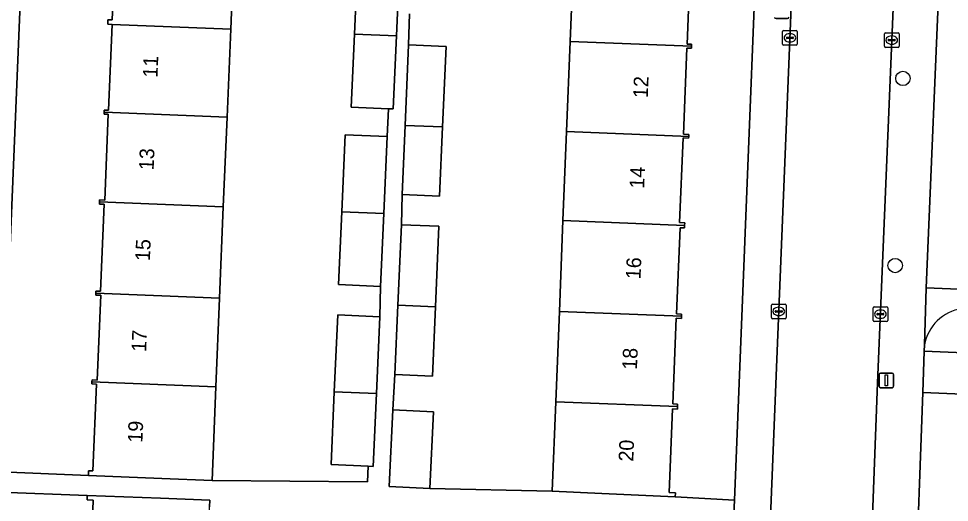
# Model space of a CAD drawing. Extents: x 160077 to 160948, y 386481 to 387498.
# Drawn here: x 160622.7 to 160686, y 386691.3 to 386724.2 of the extents above; entities that cross this region are included whole.
import ezdxf

# ---------------------------------------------------------------- set-up
doc = ezdxf.new("R2010")
doc.units = 0
for name, color, linetype in [('IMGEO_Boom', 7, 'Continuous'), ('IMGEO_Erf', 7, 'Continuous'), ('IMGEO_Groenvoorziening', 7, 'Continuous'), ('IMGEO_Kolk', 7, 'Continuous'), ('IMGEO_Lichtmast', 7, 'Continuous'), ('IMGEO_Pand', 7, 'Continuous'), ('IMGEO_Pand_nummerreeks', 7, 'Continuous'), ('IMGEO_Rijbaan_lokaal_open', 7, 'Continuous'), ('IMGEO_Voetpad_open', 7, 'Continuous')]:
    doc.layers.add(name, color=color, linetype=linetype)

msp = doc.modelspace()

# ---------------------------------------------------------------- linework, layer by layer
at = {"layer": 'IMGEO_Boom'}
for centre in [(160682.808, 386720.149), (160682.283, 386707.415)]:
    msp.add_circle(centre, 0.489, dxfattribs=at)
at = {"layer": 'IMGEO_Erf'}
for points in [[(160623.787, 386750), (160621.452, 386693.374), (160627.397, 386693.129), (160627.41, 386693.441), (160627.708, 386693.429), (160627.952, 386699.339), (160627.638, 386699.352), (160627.643, 386699.488), (160627.649, 386699.626), (160627.997, 386699.612), (160628.236, 386705.391), (160627.894, 386705.405), (160627.9, 386705.54), (160627.905, 386705.673), (160628.224, 386705.66), (160628.469, 386711.586), (160628.148, 386711.6), (160628.154, 386711.745), (160628.16, 386711.888), (160628.508, 386711.873), (160628.749, 386717.71), (160628.463, 386717.722), (160628.469, 386717.858), (160628.475, 386717.996), (160628.772, 386717.984), (160629.013, 386723.822), (160628.715, 386723.835), (160628.728, 386724.144), (160629.025, 386724.132), (160629.27, 386730.05)], [(160668.365, 386728.354), (160668.125, 386722.49), (160668.427, 386722.478), (160668.422, 386722.34), (160668.416, 386722.201), (160668.116, 386722.214), (160667.876, 386716.349), (160668.242, 386716.334), (160668.237, 386716.208), (160668.232, 386716.082), (160667.852, 386716.098), (160667.616, 386710.334), (160667.969, 386710.319), (160667.962, 386710.148), (160667.955, 386709.976), (160667.658, 386709.988), (160667.418, 386704.12), (160667.753, 386704.106), (160667.747, 386703.96), (160667.741, 386703.816), (160667.389, 386703.831), (160667.15, 386697.993), (160667.482, 386697.979), (160667.475, 386697.812), (160667.468, 386697.643), (160667.139, 386697.657), (160666.903, 386691.954), (160667.328, 386691.943), (160667.313, 386691.674), (160671.348, 386691.449), (160673.697, 386750)], [(160637.34, 386729.848), (160637.078, 386723.497), (160636.831, 386717.521), (160636.578, 386711.405), (160636.321, 386705.201), (160636.071, 386699.149), (160635.808, 386692.782), (160646.388, 386692.681), (160646.436, 386693.756), (160643.906, 386693.869), (160644.128, 386698.825), (160644.362, 386704.061), (160647.222, 386703.933), (160647.277, 386705.998), (160644.417, 386706.126), (160644.638, 386711.08), (160644.873, 386716.318), (160647.733, 386716.19), (160647.818, 386718.089), (160645.276, 386718.203), (160645.497, 386723.158), (160645.732, 386728.395)], [(160649.242, 386724.541), (160649.183, 386722.441), (160651.73, 386722.333), (160651.496, 386716.857), (160651.295, 386712.14), (160648.748, 386712.249), (160648.691, 386710.193), (160651.238, 386710.085), (160651.004, 386704.609), (160650.803, 386699.892), (160648.256, 386700.001), (160648.111, 386697.598), (160650.866, 386697.466), (160650.618, 386692.246), (160658.945, 386692.053), (160659.189, 386698.133), (160659.437, 386704.282), (160659.685, 386710.469), (160659.929, 386716.53), (160660.175, 386722.66), (160660.423, 386728.822)], [(160627.51, 386685.613), (160627.726, 386691.449), (160627.307, 386691.464), (160627.318, 386691.759), (160621.394, 386691.978)]]:
    msp.add_lwpolyline(points, dxfattribs=at)
msp.add_lwpolyline([(160733.266, 386727.02), (160685.358, 386729.013), (160684.392, 386705.888), (160736.599, 386703.746)], close=True, dxfattribs=at)
at = {"layer": 'IMGEO_Groenvoorziening'}
for points in [[(160684.282, 386702.016), (160684.265, 386701.578), (160734.304, 386699.5), (160737.203, 386679.324)], [(160686.48, 386681.453), (160733.424, 386679.476), (160732.433, 386685.483), (160721.665, 386685.947), (160722.073, 386696.59), (160730.668, 386696.179), (160730.558, 386696.843), (160684.161, 386698.783), (160683.645, 386684.533)]]:
    msp.add_lwpolyline(points, dxfattribs=at)
msp.add_lwpolyline([(160737.203, 386679.324), (160734.304, 386699.5), (160684.265, 386701.578), (160684.161, 386698.783), (160730.558, 386696.843), (160730.668, 386696.179), (160731.672, 386690.1), (160732.433, 386685.483), (160733.424, 386679.476), (160737.065, 386679.326), (160737.134, 386679.324)], close=True, dxfattribs=at)
msp.add_arc((160687.245, 386701.5), 3.007, 98.40657, 170.12144, dxfattribs=at)
at = {"layer": 'IMGEO_Kolk'}
for p, q in [((160674.62, 386722.485), (160674.62, 386723.337)), ((160674.695, 386723.411), (160675.547, 386723.411)), ((160674.879, 386722.905), (160674.879, 386722.917)), ((160675.317, 386722.868), (160674.919, 386722.868)), ((160674.922, 386722.954), (160675.32, 386722.954)), ((160675.108, 386723.191), (160675.133, 386723.191)), ((160675.363, 386722.917), (160675.363, 386722.905)), ((160675.621, 386723.337), (160675.621, 386722.485)), ((160681.55, 386722.337), (160681.55, 386723.189)), ((160681.625, 386723.263), (160682.477, 386723.263)), ((160681.852, 386722.806), (160682.25, 386722.806)), ((160682.038, 386723.043), (160682.063, 386723.043)), ((160682.551, 386723.189), (160682.551, 386722.337)), ((160675.547, 386722.411), (160674.695, 386722.411)), ((160675.131, 386722.631), (160675.106, 386722.631)), ((160682.477, 386722.263), (160681.625, 386722.263)), ((160681.809, 386722.757), (160681.809, 386722.769)), ((160682.247, 386722.72), (160681.849, 386722.72)), ((160682.061, 386722.483), (160682.036, 386722.483)), ((160682.293, 386722.769), (160682.293, 386722.757)), ((160673.864, 386703.867), (160673.864, 386704.719)), ((160673.939, 386704.793), (160674.791, 386704.793)), ((160674.352, 386704.573), (160674.377, 386704.573)), ((160674.865, 386704.719), (160674.865, 386703.867)), ((160680.775, 386703.68), (160680.775, 386704.532)), ((160680.85, 386704.606), (160681.702, 386704.606)), ((160681.776, 386704.532), (160681.776, 386703.68)), ((160674.123, 386704.287), (160674.123, 386704.299)), ((160674.561, 386704.25), (160674.163, 386704.25)), ((160674.166, 386704.336), (160674.564, 386704.336)), ((160674.375, 386704.013), (160674.35, 386704.013)), ((160674.607, 386704.299), (160674.607, 386704.287)), ((160681.034, 386704.1), (160681.034, 386704.112)), ((160681.472, 386704.063), (160681.074, 386704.063)), ((160681.077, 386704.149), (160681.475, 386704.149)), ((160681.286, 386703.826), (160681.261, 386703.826)), ((160681.263, 386704.386), (160681.288, 386704.386)), ((160681.518, 386704.112), (160681.518, 386704.1)), ((160674.791, 386703.793), (160673.939, 386703.793)), ((160681.702, 386703.606), (160680.85, 386703.606))]:
    msp.add_line(p, q, dxfattribs=at)
for points in [[(160674.62, 386722.485), (160674.62, 386723.337)], [(160674.695, 386723.411), (160675.547, 386723.411)], [(160675.621, 386723.337), (160675.621, 386722.485)], [(160681.55, 386722.337), (160681.55, 386723.189)], [(160681.625, 386723.263), (160682.477, 386723.263)], [(160682.551, 386723.189), (160682.551, 386722.337)], [(160675.547, 386722.411), (160674.695, 386722.411)], [(160682.477, 386722.263), (160681.625, 386722.263)], [(160673.864, 386703.867), (160673.864, 386704.719)], [(160673.939, 386704.793), (160674.791, 386704.793)], [(160674.865, 386704.719), (160674.865, 386703.867)], [(160680.775, 386703.68), (160680.775, 386704.532)], [(160680.85, 386704.606), (160681.702, 386704.606)], [(160681.776, 386704.532), (160681.776, 386703.68)], [(160674.791, 386703.793), (160673.939, 386703.793)], [(160681.702, 386703.606), (160680.85, 386703.606)]]:
    msp.add_lwpolyline(points, dxfattribs=at)
for centre, radius, start, end in [((160674.697, 386723.335), 0.0765, 91.55205, 178.44795), ((160674.697, 386723.335), 0.0765, 91.55205, 178.44795), ((160674.919, 386722.914), 0.0403, 85.87752, 175.75265), ((160674.916, 386722.904), 0.0366, 178.93798, 274.71019), ((160675.32, 386722.911), 0.043, 264.86636, 352.45326), ((160675.324, 386722.916), 0.0386, 1.73085, 96.63898), ((160675.545, 386723.335), 0.0765, 1.55205, 88.44795), ((160675.545, 386723.335), 0.0765, 1.55205, 88.44795), ((160681.627, 386723.187), 0.0765, 91.55205, 178.44795), ((160681.627, 386723.187), 0.0765, 91.55205, 178.44795), ((160681.849, 386722.766), 0.0403, 85.87752, 175.75265), ((160682.254, 386722.768), 0.0386, 1.73085, 96.63898), ((160682.475, 386723.187), 0.0765, 1.55205, 88.44795), ((160682.475, 386723.187), 0.0765, 1.55205, 88.44795), ((160674.697, 386722.487), 0.0765, 181.55205, 268.44795), ((160674.697, 386722.487), 0.0765, 181.55205, 268.44795), ((160675.545, 386722.487), 0.0765, 271.55205, 358.44795), ((160675.545, 386722.487), 0.0765, 271.55205, 358.44795), ((160681.627, 386722.339), 0.0765, 181.55205, 268.44795), ((160681.627, 386722.339), 0.0765, 181.55205, 268.44795), ((160681.846, 386722.756), 0.0366, 178.93798, 274.71019), ((160682.25, 386722.763), 0.043, 264.86636, 352.45326), ((160682.475, 386722.339), 0.0765, 271.55205, 358.44795), ((160682.475, 386722.339), 0.0765, 271.55205, 358.44795), ((160673.941, 386704.717), 0.0765, 91.55205, 178.44795), ((160673.941, 386704.717), 0.0765, 91.55205, 178.44795), ((160674.789, 386704.717), 0.0765, 1.55205, 88.44795), ((160674.789, 386704.717), 0.0765, 1.55205, 88.44795), ((160680.852, 386704.53), 0.0765, 91.55205, 178.44795), ((160680.852, 386704.53), 0.0765, 91.55205, 178.44795), ((160681.7, 386704.53), 0.0765, 1.55205, 88.44795), ((160681.7, 386704.53), 0.0765, 1.55205, 88.44795), ((160673.941, 386703.869), 0.0765, 181.55205, 268.44795), ((160673.941, 386703.869), 0.0765, 181.55205, 268.44795), ((160674.163, 386704.296), 0.0403, 85.87752, 175.75265), ((160674.16, 386704.286), 0.0366, 178.93798, 274.71019), ((160674.564, 386704.293), 0.043, 264.86636, 352.45326), ((160674.568, 386704.298), 0.0386, 1.73085, 96.63898), ((160674.789, 386703.869), 0.0765, 271.55205, 358.44795), ((160674.789, 386703.869), 0.0765, 271.55205, 358.44795), ((160681.074, 386704.109), 0.0403, 85.87752, 175.75265), ((160681.071, 386704.099), 0.0366, 178.93798, 274.71019), ((160681.475, 386704.106), 0.043, 264.86636, 352.45326), ((160681.479, 386704.111), 0.0386, 1.73085, 96.63898), ((160680.852, 386703.682), 0.0765, 181.55205, 268.44795), ((160680.852, 386703.682), 0.0765, 181.55205, 268.44795), ((160681.7, 386703.682), 0.0765, 271.55205, 358.44795), ((160681.7, 386703.682), 0.0765, 271.55205, 358.44795)]:
    msp.add_arc(centre, radius, start, end, dxfattribs=at)
for centre, major_axis, ratio, start_param, end_param in [((160675.107, 386722.911), (-0.387, 0.002), 0.722429, 4.712389, 7.853982), ((160675.132, 386722.911), (-0.39, 0.002), 0.717154, 1.570796, 4.712389), ((160682.037, 386722.763), (-0.387, 0.002), 0.722429, 4.712389, 7.853982), ((160682.062, 386722.763), (-0.39, 0.002), 0.717154, 1.570796, 4.712389), ((160674.351, 386704.293), (-0.387, 0.002), 0.722429, 4.712389, 7.853982), ((160674.376, 386704.293), (-0.39, 0.002), 0.717154, 1.570796, 4.712389), ((160681.262, 386704.106), (-0.387, 0.002), 0.722429, 4.712389, 7.853982), ((160681.287, 386704.106), (-0.39, 0.002), 0.717154, 1.570796, 4.712389)]:
    msp.add_ellipse(centre, major_axis=major_axis, ratio=ratio, start_param=start_param, end_param=end_param, dxfattribs=at)
at = {"layer": 'IMGEO_Lichtmast'}
for p, q in [((160674.966, 386724.222), (160674.176, 386724.222)), ((160674.176, 386724.222), (160674.966, 386724.222)), ((160681.286, 386700.097), (160682.076, 386700.097)), ((160682.076, 386700.097), (160681.286, 386700.097)), ((160681.186, 386699.197), (160681.186, 386699.997)), ((160681.186, 386699.997), (160681.186, 386699.197)), ((160682.176, 386699.997), (160682.176, 386699.197)), ((160682.176, 386699.197), (160682.176, 386699.997)), ((160682.076, 386699.097), (160681.286, 386699.097)), ((160681.286, 386699.097), (160682.076, 386699.097))]:
    msp.add_line(p, q, dxfattribs=at)
msp.add_lwpolyline([(160681.606, 386699.972), (160681.756, 386699.972), (160681.756, 386699.222), (160681.606, 386699.222), (160681.606, 386699.972)], dxfattribs=at)
for centre, start, end in [((160674.176, 386724.322), 180, 270), ((160674.176, 386724.322), 180, 270), ((160674.966, 386724.322), 270, 0), ((160674.966, 386724.322), 270, 0), ((160681.286, 386699.997), 90, 180), ((160681.286, 386699.997), 90, 180), ((160682.076, 386699.997), 0, 90), ((160682.076, 386699.997), 360, 90), ((160681.286, 386699.197), 180, 270), ((160681.286, 386699.197), 180, 270), ((160682.076, 386699.197), 270, 0), ((160682.076, 386699.197), 270, 0)]:
    msp.add_arc(centre, 0.1, start, end, dxfattribs=at)
at = {"layer": 'IMGEO_Pand'}
for points in [[(160628.956, 386730.185), (160628.951, 386730.064), (160629.27, 386730.05), (160629.025, 386724.132), (160628.728, 386724.144), (160628.715, 386723.835), (160629.013, 386723.822), (160637.078, 386723.497), (160637.34, 386729.848)], [(160660.423, 386728.822), (160660.175, 386722.66), (160668.422, 386722.34), (160668.427, 386722.478), (160668.125, 386722.49), (160668.365, 386728.354), (160668.721, 386728.34), (160668.728, 386728.5)], [(160648.592, 386728.267), (160648.001, 386728.293), (160645.732, 386728.395), (160645.497, 386723.158), (160648.359, 386723.042)], [(160629.013, 386723.822), (160628.772, 386717.984), (160628.475, 386717.996), (160628.469, 386717.858), (160636.831, 386717.521), (160637.078, 386723.497)], [(160648.359, 386723.042), (160645.497, 386723.158), (160645.276, 386718.203), (160647.818, 386718.089), (160648.136, 386718.075)], [(160651.73, 386722.333), (160649.183, 386722.441), (160648.949, 386716.956), (160651.496, 386716.857)], [(160668.237, 386716.208), (160668.242, 386716.334), (160667.876, 386716.349), (160668.116, 386722.214), (160668.416, 386722.201), (160668.422, 386722.34), (160660.175, 386722.66), (160659.929, 386716.53)], [(160636.578, 386711.405), (160636.831, 386717.521), (160628.469, 386717.858), (160628.463, 386717.722), (160628.749, 386717.71), (160628.508, 386711.873), (160628.16, 386711.888), (160628.154, 386711.745)], [(160648.748, 386712.249), (160651.295, 386712.14), (160651.496, 386716.857), (160648.949, 386716.956)], [(160667.962, 386710.148), (160667.969, 386710.319), (160667.616, 386710.334), (160667.852, 386716.098), (160668.232, 386716.082), (160668.237, 386716.208), (160659.929, 386716.53), (160659.685, 386710.469)], [(160647.733, 386716.19), (160644.873, 386716.318), (160644.638, 386711.08), (160647.5, 386710.964)], [(160628.154, 386711.745), (160628.148, 386711.6), (160628.469, 386711.586), (160628.224, 386705.66), (160627.905, 386705.673), (160627.9, 386705.54), (160636.321, 386705.201), (160636.578, 386711.405)], [(160644.417, 386706.126), (160647.277, 386705.998), (160647.5, 386710.964), (160644.638, 386711.08)], [(160651.238, 386710.085), (160648.691, 386710.193), (160648.457, 386704.707), (160651.004, 386704.609)], [(160667.747, 386703.96), (160667.753, 386704.106), (160667.418, 386704.12), (160667.658, 386709.988), (160667.955, 386709.976), (160667.962, 386710.148), (160659.685, 386710.469), (160659.437, 386704.282)], [(160627.9, 386705.54), (160627.894, 386705.405), (160628.236, 386705.391), (160627.997, 386699.612), (160627.649, 386699.626), (160627.643, 386699.488), (160636.071, 386699.149), (160636.321, 386705.201)], [(160648.256, 386700.001), (160650.803, 386699.892), (160651.004, 386704.609), (160648.457, 386704.707)], [(160647.222, 386703.933), (160644.362, 386704.061), (160644.128, 386698.825), (160646.989, 386698.71)], [(160667.475, 386697.812), (160667.482, 386697.979), (160667.15, 386697.993), (160667.389, 386703.831), (160667.741, 386703.816), (160667.747, 386703.96), (160659.437, 386704.282), (160659.189, 386698.133)], [(160627.643, 386699.488), (160627.638, 386699.352), (160627.952, 386699.339), (160627.708, 386693.429), (160627.41, 386693.441), (160627.397, 386693.129), (160632.393, 386692.923), (160635.808, 386692.782), (160636.071, 386699.149)], [(160646.989, 386698.71), (160644.128, 386698.825), (160643.906, 386693.869), (160646.436, 386693.756), (160646.766, 386693.741)], [(160659.189, 386698.133), (160658.945, 386692.053), (160662.319, 386691.9), (160667.313, 386691.674), (160667.328, 386691.943), (160666.903, 386691.954), (160667.139, 386697.657), (160667.468, 386697.643), (160667.475, 386697.812)], [(160650.618, 386692.246), (160650.866, 386697.466), (160648.111, 386697.598), (160647.863, 386692.377)], [(160635.638, 386690.983), (160635.655, 386691.451), (160632.315, 386691.574), (160627.318, 386691.759), (160627.307, 386691.464), (160627.726, 386691.449), (160627.51, 386685.613), (160627.101, 386685.628), (160627.095, 386685.46), (160635.422, 386685.151)]]:
    msp.add_lwpolyline(points, close=True, dxfattribs=at)
at = {"layer": 'IMGEO_Rijbaan_lokaal_open'}
msp.add_lwpolyline([(160680.523, 386684.347), (160681.081, 386699.432), (160682.253, 386727.666), (160683.133, 386750), (160683.261, 386753.26), (160684.339, 386779.52), (160677.356, 386779.776), (160676.66, 386759.882), (160676.246, 386750), (160675.458, 386731.188), (160674.211, 386700.474), (160673.381, 386679.573), (160672.381, 386653.071), (160671.034, 386622.001)], dxfattribs=at)
at = {"layer": 'IMGEO_Voetpad_open'}
for points in [[(160684.534, 386784.274), (160684.339, 386779.52), (160683.261, 386753.26), (160683.133, 386750), (160682.253, 386727.666), (160681.081, 386699.432), (160680.523, 386684.347)], [(160674.925, 386780.592), (160673.888, 386754.75), (160673.824, 386753.158), (160673.697, 386750), (160671.348, 386691.449), (160671.289, 386689.993), (160668.563, 386622.044)], [(160673.381, 386679.573), (160674.211, 386700.474), (160675.458, 386731.188), (160676.246, 386750), (160676.66, 386759.882), (160677.356, 386779.776), (160677.399, 386780.99)], [(160621.394, 386691.978), (160621.423, 386692.671), (160621.452, 386693.374), (160623.787, 386750), (160624.002, 386755.214), (160624.053, 386756.457), (160624.696, 386772.042), (160624.671, 386772.055), (160624.977, 386777.704)], [(160683.406, 386679.102), (160683.602, 386684.524), (160683.645, 386684.533), (160684.161, 386698.783), (160684.265, 386701.578), (160684.282, 386702.016), (160684.392, 386705.888), (160685.358, 386729.013), (160685.535, 386735.003), (160685.594, 386735.085)], [(160648.592, 386728.267), (160648.359, 386723.042), (160648.136, 386718.075), (160647.818, 386718.089), (160647.733, 386716.19), (160647.5, 386710.964), (160647.277, 386705.998), (160647.222, 386703.933), (160646.989, 386698.71), (160646.766, 386693.741), (160646.436, 386693.756), (160646.388, 386692.681), (160635.808, 386692.782), (160632.393, 386692.923), (160627.397, 386693.129), (160621.452, 386693.374)], [(160671.289, 386689.993), (160671.348, 386691.449), (160667.313, 386691.674), (160662.319, 386691.9), (160658.945, 386692.053), (160650.618, 386692.246), (160647.863, 386692.377), (160648.111, 386697.598), (160648.256, 386700.001), (160648.457, 386704.707), (160648.691, 386710.193), (160648.748, 386712.249), (160648.949, 386716.956), (160649.183, 386722.441), (160649.242, 386724.541)], [(160684.392, 386705.888), (160684.282, 386702.016)], [(160737.332, 386699.516), (160737.353, 386699.582), (160736.599, 386703.746), (160684.392, 386705.888)], [(160621.394, 386691.978), (160627.318, 386691.759), (160632.315, 386691.574), (160635.655, 386691.451), (160635.638, 386690.983)]]:
    msp.add_lwpolyline(points, dxfattribs=at)
msp.add_arc((160687.245, 386701.5), 3.007, 98.40657, 170.12144, dxfattribs=at)

# ---------------------------------------------------------------- texts
at = {"layer": 'IMGEO_Pand_nummerreeks'}
for s, rotation, p in [('11', 87.63283, (160632.097, 386720.189)), ('12', 87.71872, (160665.451, 386718.797)), ('13', 87.63283, (160631.836, 386713.891)), ('14', 87.71872, (160665.205, 386712.636)), ('15', 87.63283, (160631.581, 386707.707)), ('16', 87.71872, (160664.959, 386706.471)), ('17', 87.63283, (160631.325, 386701.523)), ('18', 87.71872, (160664.714, 386700.309)), ('19', 87.63283, (160631.069, 386695.339)), ('20', 87.71872, (160664.464, 386694.053))]:
    msp.add_text(s, height=1, rotation=rotation, dxfattribs=at).set_placement(p)

doc.saveas('drawing.dxf')
